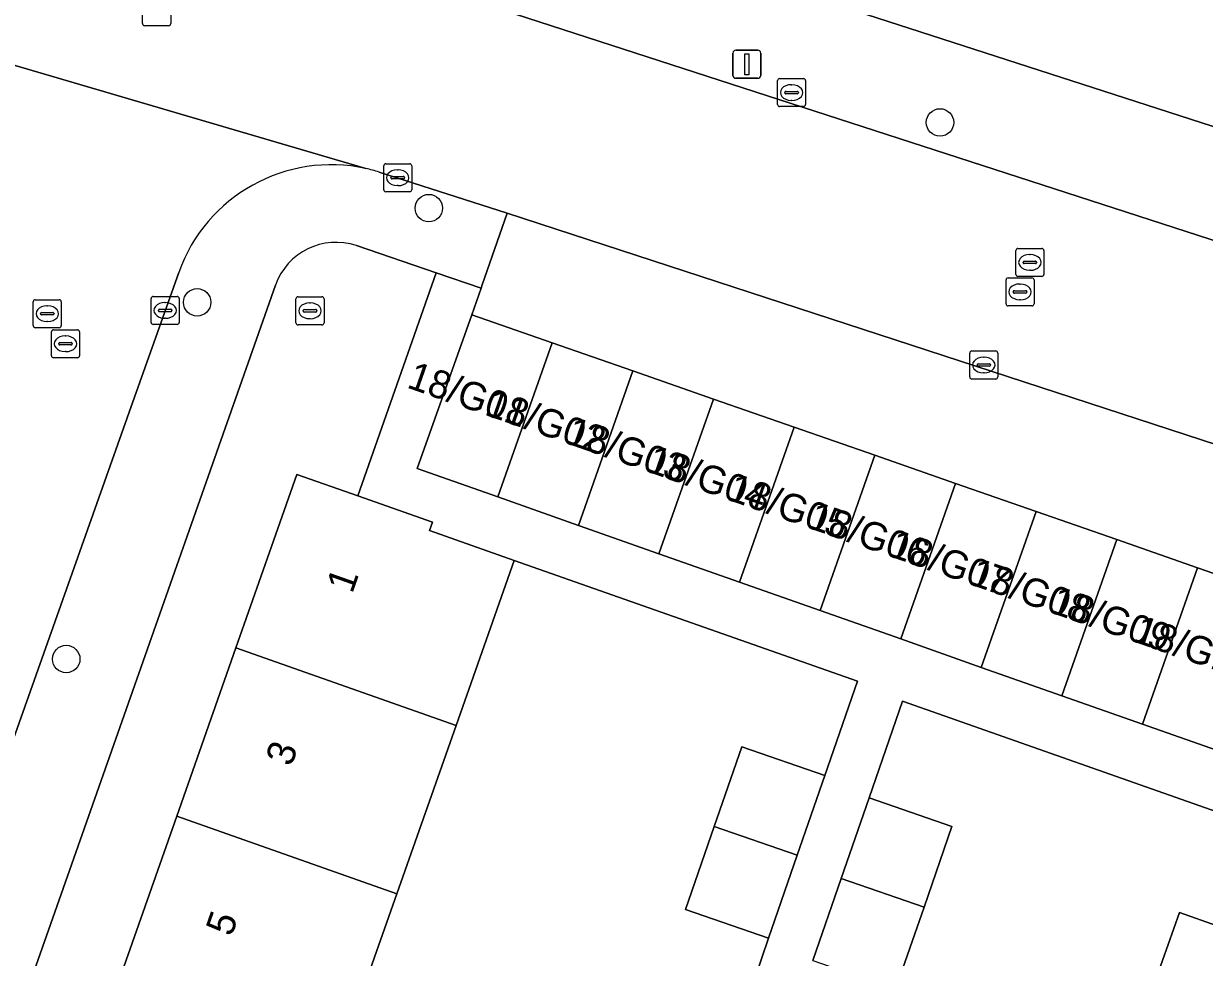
# Model space of a CAD drawing. Extents: x 163266 to 164362, y 381528 to 382286.
# Drawn here: x 163848.12 to 163890.27, y 381952.84 to 381986.15 of the extents above; entities that cross this region are included whole.
import ezdxf

# ---------------------------------------------------------------- set-up
doc = ezdxf.new("R2010")
doc.units = 0
for name, color, linetype in [('IMGEO_Boom', 7, 'Continuous'), ('IMGEO_Erf', 7, 'Continuous'), ('IMGEO_Kolk', 7, 'Continuous'), ('IMGEO_Lichtmast', 7, 'Continuous'), ('IMGEO_Pand', 7, 'Continuous'), ('IMGEO_Pand_nummerreeks', 7, 'Continuous'), ('IMGEO_Rijbaan_lokaal_open', 7, 'Continuous'), ('IMGEO_Rioolput', 7, 'Continuous'), ('IMGEO_Voetpad_open', 7, 'Continuous')]:
    doc.layers.add(name, color=color, linetype=linetype)

msp = doc.modelspace()

# ---------------------------------------------------------------- linework, layer by layer
at = {"layer": 'IMGEO_Boom'}
for centre in [(163880.83, 381982.63), (163862.586, 381979.574), (163854.319, 381976.211), (163849.647, 381963.487)]:
    msp.add_circle(centre, 0.489, dxfattribs=at)
at = {"layer": 'IMGEO_Erf'}
for points in [[(163921.004, 382029.6), (163895.961, 382038.914), (163891.376, 382026.577), (163894.534, 382025.402), (163893.615, 382022.929), (163892.325, 382019.459), (163889.167, 382020.634), (163886.782, 382014.222), (163889.961, 382013.003), (163887.771, 382007.288), (163884.649, 382008.486), (163882.422, 382002.497), (163885.572, 382001.328), (163885.079, 382000), (163884.432, 381998.256), (163883.453, 381995.618), (163880.303, 381996.787), (163876.662, 381986.975), (163899.009, 381979.765)], [(163853.588, 381957.878), (163855.703, 381963.886), (163857.879, 381970.068), (163860.052, 381969.303), (163862.853, 381977.263), (163860.004, 381978.233)], [(163857.109, 381976.819), (163842.26, 381934.657), (163845.067, 381933.668), (163847.244, 381939.852), (163849.358, 381945.86), (163851.473, 381951.869), (163853.588, 381957.878)], [(163888.571, 381952.16), (163889.376, 381954.449), (163890.722, 381953.975), (163891.993, 381957.589), (163879.494, 381961.987), (163878.299, 381958.54), (163881.257, 381957.515), (163880.26, 381954.638), (163879.246, 381951.713)]]:
    msp.add_lwpolyline(points, dxfattribs=at)
msp.add_lwpolyline([(163869.631, 381948.311), (163872.588, 381947.286), (163874.704, 381953.53), (163871.747, 381954.555), (163872.774, 381957.519), (163873.758, 381960.356), (163876.715, 381959.331), (163877.88, 381962.693), (163865.632, 381967.007), (163863.56, 381961.12), (163861.445, 381955.111), (163859.33, 381949.103), (163857.215, 381943.094), (163855.1, 381937.086), (163852.924, 381930.903), (163865.398, 381926.513), (163866.447, 381929.54), (163863.489, 381930.565), (163864.495, 381933.466), (163865.5, 381936.367), (163868.458, 381935.342), (163870.577, 381941.485), (163867.62, 381942.51), (163868.669, 381945.537)], close=True, dxfattribs=at)
msp.add_arc((163859.278, 381976.049), 2.302, 71.6171, 160.4473, dxfattribs=at)
at = {"layer": 'IMGEO_Kolk'}
for p, q in [((163875.032, 381983.268), (163875.032, 381984.12)), ((163875.107, 381984.194), (163875.959, 381984.194)), ((163876.033, 381984.12), (163876.033, 381983.268)), ((163875.291, 381983.688), (163875.291, 381983.7)), ((163875.729, 381983.651), (163875.331, 381983.651)), ((163875.334, 381983.737), (163875.732, 381983.737)), ((163875.52, 381983.974), (163875.545, 381983.974)), ((163875.775, 381983.7), (163875.775, 381983.688)), ((163875.959, 381983.194), (163875.107, 381983.194)), ((163875.543, 381983.414), (163875.518, 381983.414)), ((163860.976, 381980.229), (163860.976, 381981.081)), ((163861.051, 381981.155), (163861.903, 381981.155)), ((163861.977, 381981.081), (163861.977, 381980.229)), ((163861.235, 381980.649), (163861.235, 381980.661)), ((163861.278, 381980.698), (163861.676, 381980.698)), ((163861.464, 381980.935), (163861.489, 381980.935)), ((163861.719, 381980.661), (163861.719, 381980.649)), ((163861.673, 381980.612), (163861.275, 381980.612)), ((163861.487, 381980.375), (163861.462, 381980.375)), ((163861.903, 381980.155), (163861.051, 381980.155)), ((163852.676, 381975.495), (163852.676, 381976.347)), ((163852.751, 381976.421), (163853.603, 381976.421)), ((163853.164, 381976.201), (163853.189, 381976.201)), ((163853.677, 381976.347), (163853.677, 381975.495)), ((163852.935, 381975.915), (163852.935, 381975.927)), ((163853.373, 381975.878), (163852.975, 381975.878)), ((163852.978, 381975.964), (163853.376, 381975.964)), ((163853.187, 381975.641), (163853.162, 381975.641)), ((163853.419, 381975.927), (163853.419, 381975.915)), ((163853.603, 381975.421), (163852.751, 381975.421)), ((163881.892, 381973.549), (163881.892, 381974.401)), ((163881.967, 381974.475), (163882.819, 381974.475)), ((163882.893, 381974.401), (163882.893, 381973.549)), ((163882.151, 381973.969), (163882.151, 381973.981)), ((163882.589, 381973.932), (163882.191, 381973.932)), ((163882.194, 381974.018), (163882.592, 381974.018)), ((163882.38, 381974.255), (163882.405, 381974.255)), ((163882.635, 381973.981), (163882.635, 381973.969)), ((163882.403, 381973.695), (163882.378, 381973.695)), ((163882.819, 381973.475), (163881.967, 381973.475))]:
    msp.add_line(p, q, dxfattribs=at)
for points in [[(163875.032, 381983.268), (163875.032, 381984.12)], [(163875.107, 381984.194), (163875.959, 381984.194)], [(163876.033, 381984.12), (163876.033, 381983.268)], [(163875.959, 381983.194), (163875.107, 381983.194)], [(163860.976, 381980.229), (163860.976, 381981.081)], [(163861.051, 381981.155), (163861.903, 381981.155)], [(163861.977, 381981.081), (163861.977, 381980.229)], [(163861.903, 381980.155), (163861.051, 381980.155)], [(163852.676, 381975.495), (163852.676, 381976.347)], [(163852.751, 381976.421), (163853.603, 381976.421)], [(163853.677, 381976.347), (163853.677, 381975.495)], [(163853.603, 381975.421), (163852.751, 381975.421)], [(163881.892, 381973.549), (163881.892, 381974.401)], [(163881.967, 381974.475), (163882.819, 381974.475)], [(163882.893, 381974.401), (163882.893, 381973.549)], [(163882.819, 381973.475), (163881.967, 381973.475)]]:
    msp.add_lwpolyline(points, dxfattribs=at)
for centre, radius, start, end in [((163875.109, 381984.118), 0.0765, 91.552, 178.448), ((163875.109, 381984.118), 0.0765, 91.552, 178.448), ((163875.957, 381984.118), 0.0765, 1.552, 88.448), ((163875.957, 381984.118), 0.0765, 1.552, 88.448), ((163875.331, 381983.697), 0.0403, 85.8775, 175.7526), ((163875.328, 381983.687), 0.0366, 178.938, 274.7102), ((163875.732, 381983.694), 0.043, 264.8664, 352.4533), ((163875.736, 381983.699), 0.0386, 1.7309, 96.639), ((163875.109, 381983.27), 0.0765, 181.552, 268.448), ((163875.109, 381983.27), 0.0765, 181.552, 268.448), ((163875.957, 381983.27), 0.0765, 271.552, 358.448), ((163875.957, 381983.27), 0.0765, 271.552, 358.448), ((163861.053, 381981.079), 0.0765, 91.552, 178.448), ((163861.053, 381981.079), 0.0765, 91.552, 178.448), ((163861.901, 381981.079), 0.0765, 1.552, 88.448), ((163861.901, 381981.079), 0.0765, 1.552, 88.448), ((163861.275, 381980.658), 0.0403, 85.8775, 175.7526), ((163861.68, 381980.66), 0.0386, 1.7309, 96.639), ((163861.272, 381980.648), 0.0366, 178.938, 274.7102), ((163861.676, 381980.655), 0.043, 264.8664, 352.4533), ((163861.053, 381980.231), 0.0765, 181.552, 268.448), ((163861.053, 381980.231), 0.0765, 181.552, 268.448), ((163861.901, 381980.231), 0.0765, 271.552, 358.448), ((163861.901, 381980.231), 0.0765, 271.552, 358.448), ((163852.753, 381976.345), 0.0765, 91.552, 178.448), ((163852.753, 381976.345), 0.0765, 91.552, 178.448), ((163853.601, 381976.345), 0.0765, 1.552, 88.448), ((163853.601, 381976.345), 0.0765, 1.552, 88.448), ((163852.975, 381975.924), 0.0403, 85.8775, 175.7526), ((163852.972, 381975.914), 0.0366, 178.938, 274.7102), ((163853.376, 381975.921), 0.043, 264.8664, 352.4533), ((163853.38, 381975.926), 0.0386, 1.7309, 96.639), ((163852.753, 381975.497), 0.0765, 181.552, 268.448), ((163852.753, 381975.497), 0.0765, 181.552, 268.448), ((163853.601, 381975.497), 0.0765, 271.552, 358.448), ((163853.601, 381975.497), 0.0765, 271.552, 358.448), ((163881.969, 381974.399), 0.0765, 91.552, 178.448), ((163881.969, 381974.399), 0.0765, 91.552, 178.448), ((163882.817, 381974.399), 0.0765, 1.552, 88.448), ((163882.817, 381974.399), 0.0765, 1.552, 88.448), ((163882.191, 381973.978), 0.0403, 85.8775, 175.7526), ((163882.188, 381973.968), 0.0366, 178.938, 274.7102), ((163882.592, 381973.975), 0.043, 264.8664, 352.4533), ((163882.596, 381973.98), 0.0386, 1.7309, 96.639), ((163881.969, 381973.551), 0.0765, 181.552, 268.448), ((163881.969, 381973.551), 0.0765, 181.552, 268.448), ((163882.817, 381973.551), 0.0765, 271.552, 358.448), ((163882.817, 381973.551), 0.0765, 271.552, 358.448)]:
    msp.add_arc(centre, radius, start, end, dxfattribs=at)
for centre, major_axis, ratio, start_param, end_param in [((163875.519, 381983.694), (-0.387, 0.002), 0.722429, 4.712389, 7.853982), ((163875.544, 381983.694), (-0.39, 0.002), 0.717154, 1.570796, 4.712389), ((163861.463, 381980.655), (-0.387, 0.002), 0.722429, 4.712389, 7.853982), ((163861.488, 381980.655), (-0.39, 0.002), 0.717154, 1.570796, 4.712389), ((163853.163, 381975.921), (-0.387, 0.002), 0.722429, 4.712389, 7.853982), ((163853.188, 381975.921), (-0.39, 0.002), 0.717154, 1.570796, 4.712389), ((163882.379, 381973.975), (-0.387, 0.002), 0.722429, 4.712389, 7.853982), ((163882.404, 381973.975), (-0.39, 0.002), 0.717154, 1.570796, 4.712389)]:
    msp.add_ellipse(centre, major_axis=major_axis, ratio=ratio, start_param=start_param, end_param=end_param, dxfattribs=at)
at = {"layer": 'IMGEO_Lichtmast'}
for p, q in [((163873.44, 381984.303), (163873.44, 381985.103)), ((163873.44, 381985.103), (163873.44, 381984.303)), ((163873.54, 381985.203), (163874.33, 381985.203)), ((163874.33, 381985.203), (163873.54, 381985.203)), ((163874.43, 381985.103), (163874.43, 381984.303)), ((163874.43, 381984.303), (163874.43, 381985.103)), ((163874.33, 381984.203), (163873.54, 381984.203)), ((163873.54, 381984.203), (163874.33, 381984.203))]:
    msp.add_line(p, q, dxfattribs=at)
msp.add_lwpolyline([(163873.86, 381985.078), (163874.01, 381985.078), (163874.01, 381984.328), (163873.86, 381984.328), (163873.86, 381985.078)], dxfattribs=at)
for centre, start, end in [((163873.54, 381985.103), 90, 180), ((163873.54, 381985.103), 90, 180), ((163874.33, 381985.103), 0, 90), ((163874.33, 381985.103), 360, 90), ((163873.54, 381984.303), 180, 270), ((163873.54, 381984.303), 180, 270), ((163874.33, 381984.303), 270, 0), ((163874.33, 381984.303), 270, 0)]:
    msp.add_arc(centre, 0.1, start, end, dxfattribs=at)
at = {"layer": 'IMGEO_Pand'}
for points in [[(163862.172, 381970.283), (163865.048, 381969.269), (163866.986, 381974.768), (163864.122, 381975.765)], [(163867.924, 381968.256), (163869.866, 381973.765), (163866.986, 381974.768), (163865.048, 381969.269)], [(163870.8, 381967.242), (163872.745, 381972.762), (163869.866, 381973.765), (163867.924, 381968.256)], [(163875.625, 381971.76), (163872.745, 381972.762), (163870.8, 381967.242), (163873.676, 381966.229)], [(163878.505, 381970.757), (163875.625, 381971.76), (163873.676, 381966.229), (163876.552, 381965.215)], [(163876.552, 381965.215), (163879.428, 381964.202), (163881.384, 381969.754), (163878.505, 381970.757)], [(163865.632, 381967.007), (163862.608, 381968.072), (163862.712, 381968.367), (163860.052, 381969.303), (163857.879, 381970.068), (163855.703, 381963.886), (163863.56, 381961.12)], [(163882.303, 381963.188), (163884.264, 381968.751), (163881.384, 381969.754), (163879.428, 381964.202)], [(163885.179, 381962.174), (163887.144, 381967.749), (163884.264, 381968.751), (163882.303, 381963.188)], [(163888.055, 381961.161), (163890.024, 381966.746), (163887.144, 381967.749), (163885.179, 381962.174)], [(163890.931, 381960.147), (163892.903, 381965.743), (163890.024, 381966.746), (163888.055, 381961.161)], [(163853.588, 381957.878), (163861.445, 381955.111), (163863.56, 381961.12), (163855.703, 381963.886)], [(163872.774, 381957.519), (163875.732, 381956.494), (163876.715, 381959.331), (163873.758, 381960.356)], [(163880.26, 381954.638), (163881.257, 381957.515), (163878.299, 381958.54), (163877.302, 381955.664)], [(163853.588, 381957.878), (163851.473, 381951.869), (163859.33, 381949.103), (163861.445, 381955.111)], [(163872.774, 381957.519), (163871.747, 381954.555), (163874.704, 381953.53), (163875.732, 381956.494)], [(163900.053, 381955.236), (163897.424, 381956.16), (163895.455, 381956.853), (163895.304, 381956.424), (163891.993, 381957.589), (163890.722, 381953.975), (163889.376, 381954.449), (163888.571, 381952.16), (163898.118, 381948.809), (163898.987, 381951.28), (163898.698, 381951.381)], [(163880.26, 381954.638), (163877.302, 381955.664), (163876.288, 381952.738), (163879.246, 381951.713)]]:
    msp.add_lwpolyline(points, close=True, dxfattribs=at)
at = {"layer": 'IMGEO_Rijbaan_lokaal_open'}
for points in [[(163924.887, 381957.526), (163927.633, 381962.707), (163916.926, 381969.068), (163914.704, 381970.381), (163896.886, 381976.383), (163849.853, 381991.631)], [(163844.613, 381985.6), (163860.342, 381980.985)], [(163860.342, 381980.985), (163844.613, 381985.6)], [(163860.818, 381980.86), (163865.382, 381979.397), (163901.134, 381967.725), (163906.341, 381966.025)], [(163851.893, 381972.292), (163853.659, 381977.276)], [(163809.12, 381850.886), (163812.108, 381859.471), (163812.258, 381859.902), (163813.491, 381863.443), (163822.962, 381890.652), (163851.893, 381972.292)]]:
    msp.add_lwpolyline(points, dxfattribs=at)
for centre, radius, start, end in [((163859.108, 381975.333), 5.785, 77.6829, 160.3768), ((163859.201, 381975.671), 5.435, 72.6909, 77.8812)]:
    msp.add_arc(centre, radius, start, end, dxfattribs=at)
at = {"layer": 'IMGEO_Rioolput'}
for p, q in [((163852.373, 381986.153), (163852.373, 381987.005)), ((163853.374, 381987.005), (163853.374, 381986.153)), ((163853.3, 381986.079), (163852.448, 381986.079)), ((163883.612, 381978.134), (163884.464, 381978.134)), ((163883.537, 381977.208), (163883.537, 381978.06)), ((163884.025, 381977.914), (163884.05, 381977.914)), ((163884.538, 381978.06), (163884.538, 381977.208)), ((163883.796, 381977.628), (163883.796, 381977.64)), ((163884.234, 381977.591), (163883.836, 381977.591)), ((163883.839, 381977.677), (163884.237, 381977.677)), ((163884.048, 381977.354), (163884.023, 381977.354)), ((163884.28, 381977.64), (163884.28, 381977.628)), ((163883.186, 381976.157), (163883.186, 381977.009)), ((163883.261, 381977.083), (163884.113, 381977.083)), ((163884.464, 381977.134), (163883.612, 381977.134)), ((163884.187, 381977.009), (163884.187, 381976.157)), ((163883.445, 381976.577), (163883.445, 381976.589)), ((163883.883, 381976.54), (163883.485, 381976.54)), ((163883.488, 381976.626), (163883.886, 381976.626)), ((163883.674, 381976.863), (163883.699, 381976.863)), ((163883.929, 381976.589), (163883.929, 381976.577)), ((163848.468, 381975.379), (163848.468, 381976.231)), ((163848.543, 381976.305), (163849.395, 381976.305)), ((163848.956, 381976.085), (163848.981, 381976.085)), ((163849.469, 381976.231), (163849.469, 381975.379)), ((163857.845, 381975.482), (163857.845, 381976.334)), ((163857.92, 381976.408), (163858.772, 381976.408)), ((163858.333, 381976.188), (163858.358, 381976.188)), ((163858.846, 381976.334), (163858.846, 381975.482)), ((163884.113, 381976.083), (163883.261, 381976.083)), ((163883.697, 381976.303), (163883.672, 381976.303)), ((163848.727, 381975.799), (163848.727, 381975.811)), ((163849.165, 381975.762), (163848.767, 381975.762)), ((163848.77, 381975.848), (163849.168, 381975.848)), ((163849.211, 381975.811), (163849.211, 381975.799)), ((163858.104, 381975.902), (163858.104, 381975.914)), ((163858.542, 381975.865), (163858.144, 381975.865)), ((163858.147, 381975.951), (163858.545, 381975.951)), ((163858.356, 381975.628), (163858.331, 381975.628)), ((163858.588, 381975.914), (163858.588, 381975.902)), ((163849.395, 381975.305), (163848.543, 381975.305)), ((163848.979, 381975.525), (163848.954, 381975.525)), ((163849.194, 381975.233), (163850.046, 381975.233)), ((163858.772, 381975.408), (163857.92, 381975.408)), ((163849.119, 381974.307), (163849.119, 381975.159)), ((163849.421, 381974.776), (163849.819, 381974.776)), ((163849.607, 381975.013), (163849.632, 381975.013)), ((163850.12, 381975.159), (163850.12, 381974.307)), ((163849.378, 381974.727), (163849.378, 381974.739)), ((163849.816, 381974.69), (163849.418, 381974.69)), ((163849.63, 381974.453), (163849.605, 381974.453)), ((163849.862, 381974.739), (163849.862, 381974.727)), ((163850.046, 381974.233), (163849.194, 381974.233))]:
    msp.add_line(p, q, dxfattribs=at)
for points in [[(163852.373, 381986.153), (163852.373, 381987.005)], [(163853.374, 381987.005), (163853.374, 381986.153)], [(163853.3, 381986.079), (163852.448, 381986.079)], [(163883.612, 381978.134), (163884.464, 381978.134)], [(163883.537, 381977.208), (163883.537, 381978.06)], [(163884.538, 381978.06), (163884.538, 381977.208)], [(163883.186, 381976.157), (163883.186, 381977.009)], [(163883.261, 381977.083), (163884.113, 381977.083)], [(163884.464, 381977.134), (163883.612, 381977.134)], [(163884.187, 381977.009), (163884.187, 381976.157)], [(163848.468, 381975.379), (163848.468, 381976.231)], [(163848.543, 381976.305), (163849.395, 381976.305)], [(163849.469, 381976.231), (163849.469, 381975.379)], [(163857.845, 381975.482), (163857.845, 381976.334)], [(163857.92, 381976.408), (163858.772, 381976.408)], [(163858.846, 381976.334), (163858.846, 381975.482)], [(163884.113, 381976.083), (163883.261, 381976.083)], [(163849.395, 381975.305), (163848.543, 381975.305)], [(163849.194, 381975.233), (163850.046, 381975.233)], [(163858.772, 381975.408), (163857.92, 381975.408)], [(163849.119, 381974.307), (163849.119, 381975.159)], [(163850.12, 381975.159), (163850.12, 381974.307)], [(163850.046, 381974.233), (163849.194, 381974.233)]]:
    msp.add_lwpolyline(points, dxfattribs=at)
for centre, radius, start, end in [((163852.45, 381986.155), 0.0765, 181.552, 268.448), ((163852.45, 381986.155), 0.0765, 181.552, 268.448), ((163853.298, 381986.155), 0.0765, 271.552, 358.448), ((163853.298, 381986.155), 0.0765, 271.552, 358.448), ((163883.614, 381978.058), 0.0765, 91.552, 178.448), ((163883.614, 381978.058), 0.0765, 91.552, 178.448), ((163884.462, 381978.058), 0.0765, 1.552, 88.448), ((163884.462, 381978.058), 0.0765, 1.552, 88.448), ((163883.836, 381977.637), 0.0403, 85.8775, 175.7526), ((163883.833, 381977.627), 0.0366, 178.938, 274.7102), ((163884.237, 381977.634), 0.043, 264.8664, 352.4533), ((163884.241, 381977.639), 0.0386, 1.7309, 96.639), ((163883.263, 381977.007), 0.0765, 91.552, 178.448), ((163883.263, 381977.007), 0.0765, 91.552, 178.448), ((163883.614, 381977.21), 0.0765, 181.552, 268.448), ((163883.614, 381977.21), 0.0765, 181.552, 268.448), ((163884.111, 381977.007), 0.0765, 1.552, 88.448), ((163884.111, 381977.007), 0.0765, 1.552, 88.448), ((163884.462, 381977.21), 0.0765, 271.552, 358.448), ((163884.462, 381977.21), 0.0765, 271.552, 358.448), ((163883.485, 381976.586), 0.0403, 85.8775, 175.7526), ((163883.482, 381976.576), 0.0366, 178.938, 274.7102), ((163883.886, 381976.583), 0.043, 264.8664, 352.4533), ((163883.89, 381976.588), 0.0386, 1.7309, 96.639), ((163848.545, 381976.229), 0.0765, 91.552, 178.448), ((163848.545, 381976.229), 0.0765, 91.552, 178.448), ((163849.393, 381976.229), 0.0765, 1.552, 88.448), ((163849.393, 381976.229), 0.0765, 1.552, 88.448), ((163857.922, 381976.332), 0.0765, 91.552, 178.448), ((163857.922, 381976.332), 0.0765, 91.552, 178.448), ((163858.77, 381976.332), 0.0765, 1.552, 88.448), ((163858.77, 381976.332), 0.0765, 1.552, 88.448), ((163883.263, 381976.159), 0.0765, 181.552, 268.448), ((163883.263, 381976.159), 0.0765, 181.552, 268.448), ((163884.111, 381976.159), 0.0765, 271.552, 358.448), ((163884.111, 381976.159), 0.0765, 271.552, 358.448), ((163848.767, 381975.808), 0.0403, 85.8775, 175.7526), ((163848.764, 381975.798), 0.0366, 178.938, 274.7102), ((163849.168, 381975.805), 0.043, 264.8664, 352.4533), ((163849.172, 381975.81), 0.0386, 1.7309, 96.639), ((163858.144, 381975.911), 0.0403, 85.8775, 175.7526), ((163858.141, 381975.901), 0.0366, 178.938, 274.7102), ((163858.545, 381975.908), 0.043, 264.8664, 352.4533), ((163858.549, 381975.913), 0.0386, 1.7309, 96.639), ((163848.545, 381975.381), 0.0765, 181.552, 268.448), ((163848.545, 381975.381), 0.0765, 181.552, 268.448), ((163849.196, 381975.157), 0.0765, 91.552, 178.448), ((163849.196, 381975.157), 0.0765, 91.552, 178.448), ((163849.393, 381975.381), 0.0765, 271.552, 358.448), ((163849.393, 381975.381), 0.0765, 271.552, 358.448), ((163850.044, 381975.157), 0.0765, 1.552, 88.448), ((163850.044, 381975.157), 0.0765, 1.552, 88.448), ((163857.922, 381975.484), 0.0765, 181.552, 268.448), ((163857.922, 381975.484), 0.0765, 181.552, 268.448), ((163858.77, 381975.484), 0.0765, 271.552, 358.448), ((163858.77, 381975.484), 0.0765, 271.552, 358.448), ((163849.418, 381974.736), 0.0403, 85.8775, 175.7526), ((163849.823, 381974.738), 0.0386, 1.7309, 96.639), ((163849.415, 381974.726), 0.0366, 178.938, 274.7102), ((163849.819, 381974.733), 0.043, 264.8664, 352.4533), ((163849.196, 381974.309), 0.0765, 181.552, 268.448), ((163849.196, 381974.309), 0.0765, 181.552, 268.448), ((163850.044, 381974.309), 0.0765, 271.552, 358.448), ((163850.044, 381974.309), 0.0765, 271.552, 358.448)]:
    msp.add_arc(centre, radius, start, end, dxfattribs=at)
for centre, major_axis, ratio, start_param, end_param in [((163884.024, 381977.634), (-0.387, 0.002), 0.722429, 4.712389, 7.853982), ((163884.049, 381977.634), (-0.39, 0.002), 0.717154, 1.570796, 4.712389), ((163883.673, 381976.583), (-0.387, 0.002), 0.722429, 4.712389, 7.853982), ((163883.698, 381976.583), (-0.39, 0.002), 0.717154, 1.570796, 4.712389), ((163848.955, 381975.805), (-0.387, 0.002), 0.722429, 4.712389, 7.853982), ((163848.98, 381975.805), (-0.39, 0.002), 0.717154, 1.570796, 4.712389), ((163858.332, 381975.908), (-0.387, 0.002), 0.722429, 4.712389, 7.853982), ((163858.357, 381975.908), (-0.39, 0.002), 0.717154, 1.570796, 4.712389), ((163849.606, 381974.733), (-0.387, 0.002), 0.722429, 4.712389, 7.853982), ((163849.631, 381974.733), (-0.39, 0.002), 0.717154, 1.570796, 4.712389)]:
    msp.add_ellipse(centre, major_axis=major_axis, ratio=ratio, start_param=start_param, end_param=end_param, dxfattribs=at)
at = {"layer": 'IMGEO_Voetpad_open'}
for points in [[(163836.291, 382000), (163784.545, 382016.624), (163783.143, 382017.074), (163773.431, 382020.194), (163770.69, 382021.032), (163765.086, 382022.744), (163758.349, 382025.147), (163757.318, 382021.706), (163762.591, 382019.997), (163809.167, 382005.041), (163831.384, 381997.714), (163849.853, 381991.631), (163896.886, 381976.383)], [(163899.009, 381979.765), (163876.662, 381986.975), (163875.242, 381987.433), (163836.291, 382000)], [(163865.382, 381979.397), (163860.818, 381980.86)], [(163860.004, 381978.233), (163862.853, 381977.263), (163864.454, 381976.718), (163864.496, 381976.839), (163865.382, 381979.397)], [(163853.659, 381977.276), (163851.893, 381972.292), (163822.962, 381890.652), (163813.491, 381863.443), (163813.963, 381863.277), (163812.73, 381859.736), (163812.258, 381859.902), (163812.108, 381859.471), (163809.12, 381850.886)], [(163890.931, 381960.147), (163888.055, 381961.161), (163885.179, 381962.174), (163882.303, 381963.188), (163879.428, 381964.202), (163876.552, 381965.215), (163873.676, 381966.229), (163870.8, 381967.242), (163867.924, 381968.256), (163865.048, 381969.269), (163862.172, 381970.283), (163864.122, 381975.765), (163864.454, 381976.718), (163862.853, 381977.263), (163860.052, 381969.303), (163862.712, 381968.367), (163862.608, 381968.072), (163865.632, 381967.007), (163877.88, 381962.693), (163876.715, 381959.331), (163875.732, 381956.494), (163874.704, 381953.53), (163872.588, 381947.286)], [(163810.542, 381844.716), (163811.418, 381847.575), (163813.29, 381852.548), (163815.906, 381859.829), (163829.933, 381899.655), (163830.798, 381902.112), (163841.412, 381932.249), (163842.26, 381934.657), (163857.109, 381976.819)], [(163876.288, 381952.738), (163877.302, 381955.664), (163878.299, 381958.54), (163879.494, 381961.987), (163891.993, 381957.589)]]:
    msp.add_lwpolyline(points, dxfattribs=at)
msp.add_lwpolyline([(163865.382, 381979.397), (163864.496, 381976.839), (163864.454, 381976.718), (163864.122, 381975.765), (163866.986, 381974.768), (163869.866, 381973.765), (163872.745, 381972.762), (163875.625, 381971.76), (163878.505, 381970.757), (163881.384, 381969.754), (163884.264, 381968.751), (163887.144, 381967.749), (163890.024, 381966.746), (163892.903, 381965.743), (163895.783, 381964.74), (163898.682, 381963.731), (163899.056, 381964.805), (163899.419, 381965.709), (163900.297, 381965.405), (163900.368, 381965.565), (163901.134, 381967.725)], close=True, dxfattribs=at)
for centre, radius, start, end in [((163859.108, 381975.333), 5.785, 77.6829, 160.3768), ((163859.201, 381975.671), 5.435, 72.6909, 77.8812), ((163859.278, 381976.049), 2.302, 71.6171, 160.4473)]:
    msp.add_arc(centre, radius, start, end, dxfattribs=at)

# ---------------------------------------------------------------- texts
at = {"layer": 'IMGEO_Pand_nummerreeks'}
for s, rotation, p in [('18/G01', 340.7407, (163861.764, 381973.182)), ('18/G02', 340.7407, (163864.536, 381972.213)), ('18/G03', 340.7407, (163867.424, 381971.204)), ('18/G04', 340.7407, (163870.306, 381970.197)), ('18/G05', 340.7407, (163873.188, 381969.19)), ('18/G06', 340.7407, (163876.07, 381968.183)), ('18/G07', 340.7407, (163878.952, 381967.176)), ('18/G08', 340.7407, (163881.837, 381966.169)), ('1', 70.6113, (163859.852, 381965.794)), ('18/G09', 340.7407, (163884.713, 381965.164)), ('18/G10', 340.7407, (163887.687, 381964.124)), ('3', 70.6091, (163857.678, 381959.619)), ('5', 70.6091, (163855.543, 381953.552))]:
    msp.add_text(s, height=1, rotation=rotation, dxfattribs=at).set_placement(p)

doc.saveas('drawing.dxf')
